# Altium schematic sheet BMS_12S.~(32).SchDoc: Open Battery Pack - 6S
size A3; Author: Morgane Vallée; Revision: 1.0; SheetNumber: 3; SheetTotal: 4
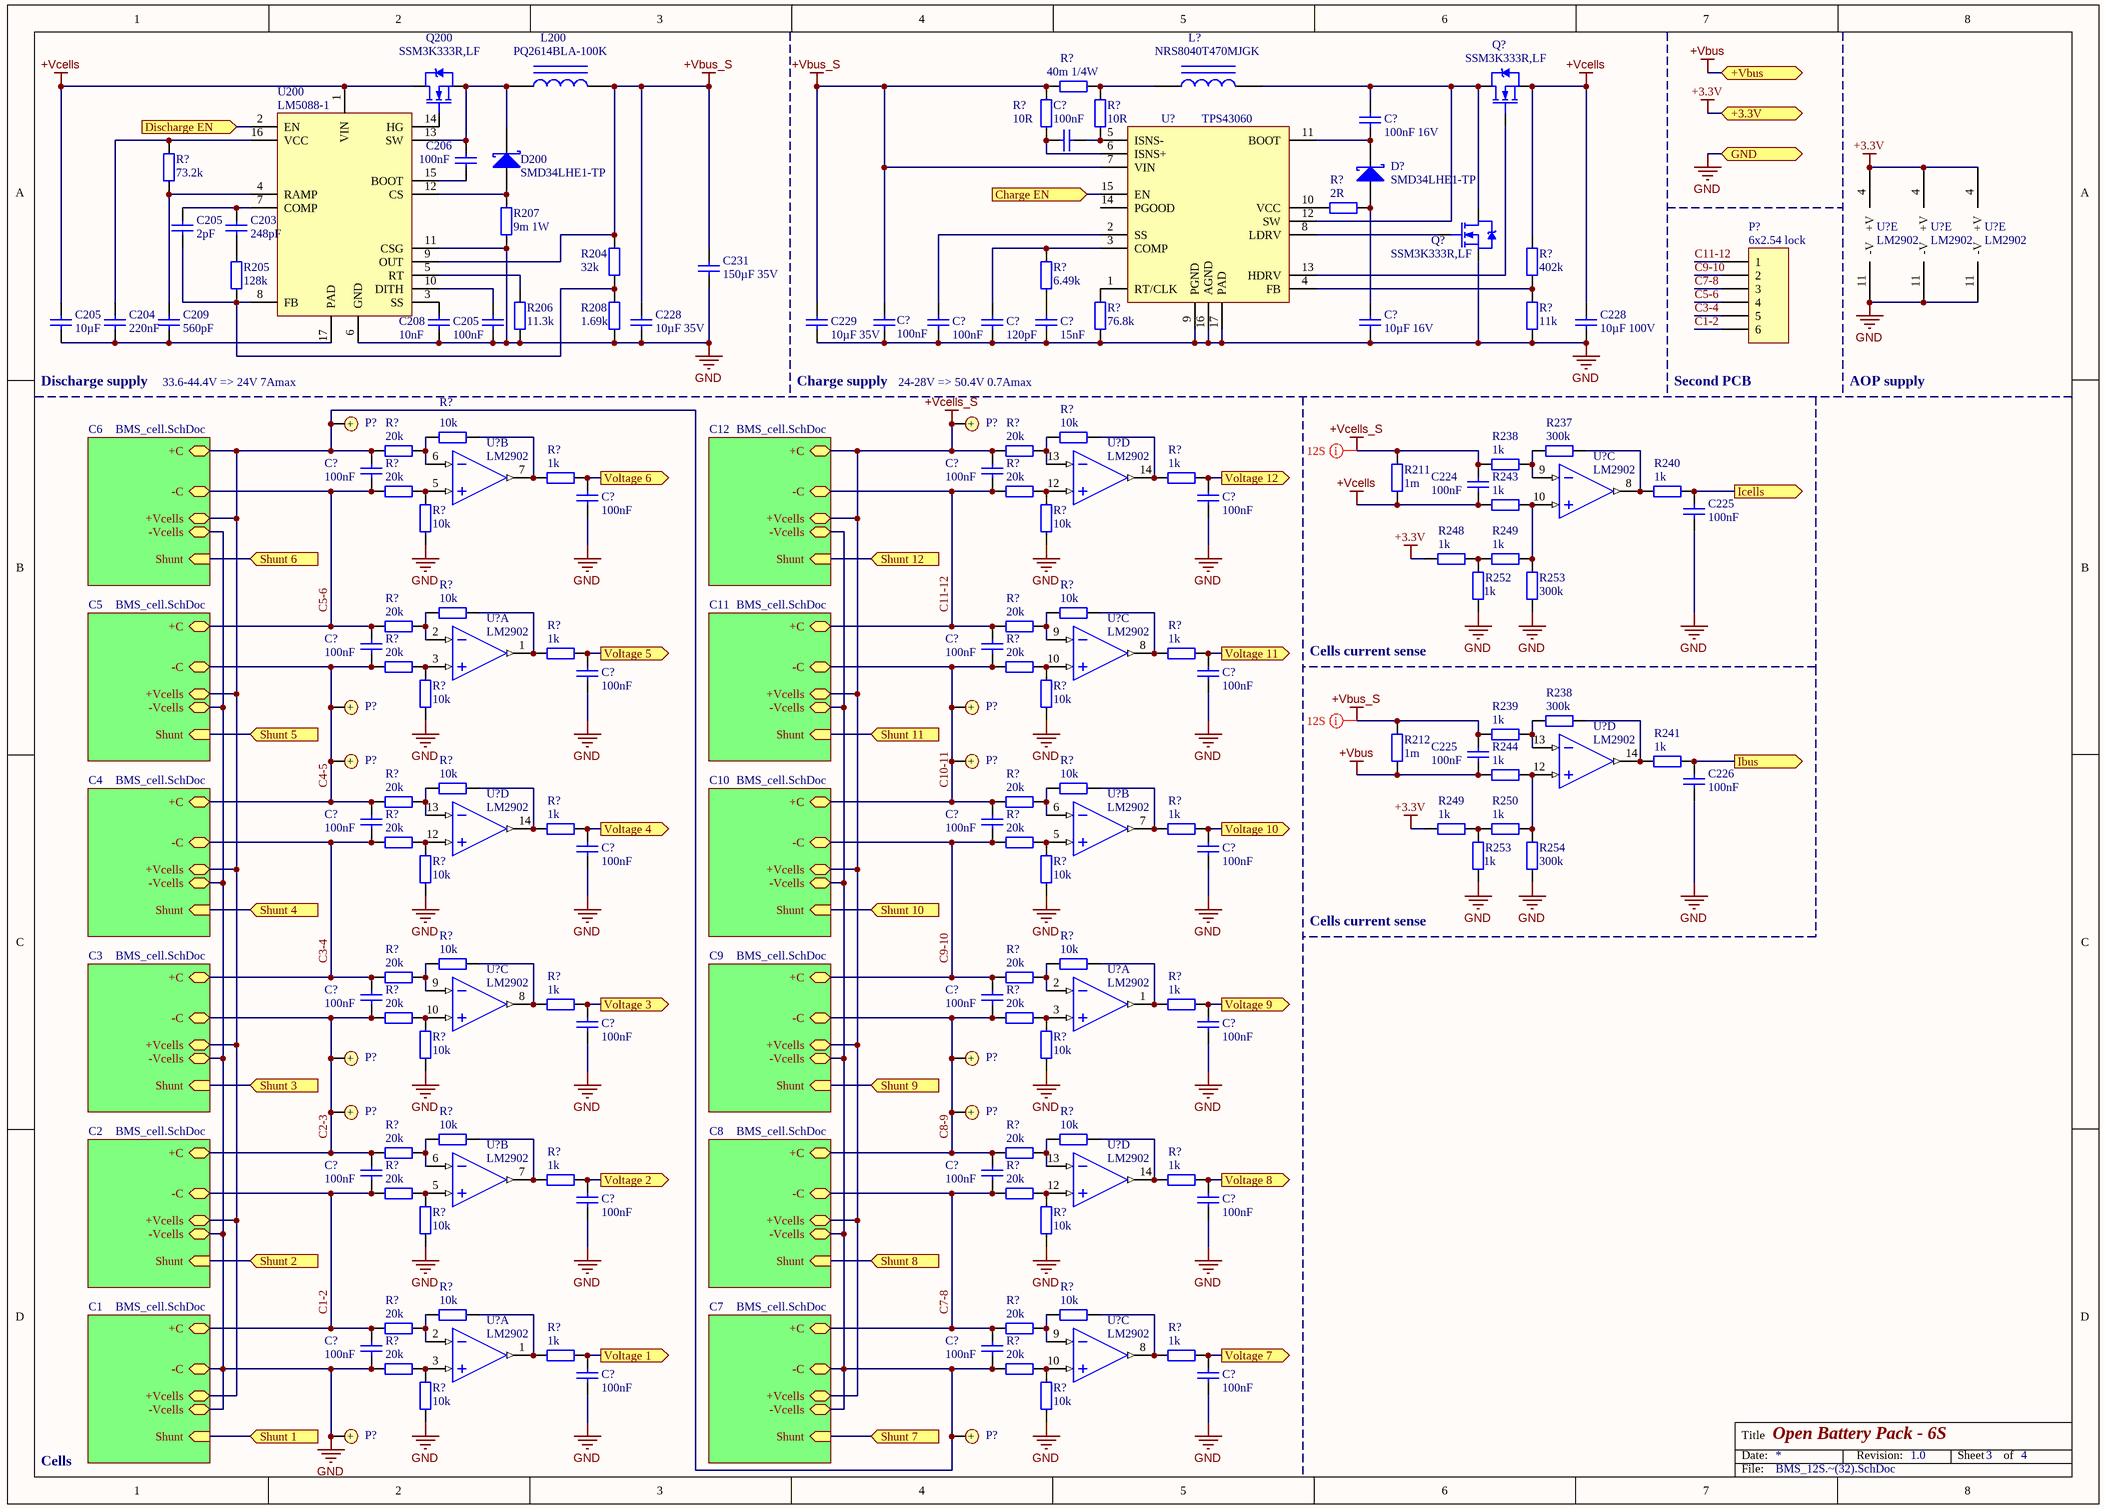
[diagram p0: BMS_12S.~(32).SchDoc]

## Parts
(Parts that share a designator on the sheet are numbered #1, #2 ... from top to bottom, then left to right.)
C203  248pF  [C0603]
C204  220nF  [C0603]
C205#1  2pF  [C0603]
C205#2  10µF  [C0603]
C205#3  100nF  [C0603]
C206  100nF  [C0603]
C208  10nF  [C0603]
C209  560pF  [C0603]
C224  100nF  [C0603]
C225#1  100nF  [C0603]
C225#2  100nF  [C0603]
C226  100nF  [C0603]
C228#1  10µF 35V  [C0603]
C228#2  10µF 100V  [C0603]
C229  10µF 35V  [C0603]
C231  150µF 35V  [C0603]
C?#1  100nF 16V  [C0603]
C?#2  100nF  [C0603]
C?#3  100nF  [C0603]
C?#4  120pF  [C0603]
C?#5  15nF  [C0603]
C?#6  10µF 16V  [C0805]
C?#7  100nF  [C0603]
C?#8  100nF  [C0603]
C?#9  100nF  [C0603]
C?#10  100nF  [C0603]
C?#11  100nF  [C0603]
C?#12  100nF  [C0603]
C?#13  100nF  [C0603]
C?#14  100nF  [C0603]
C?#15  100nF  [C0603]
C?#16  100nF  [C0603]
C?#17  100nF  [C0603]
C?#18  100nF  [C0603]
C?#19  100nF  [C0603]
C?#20  100nF  [C0603]
C?#21  100nF  [C0603]
C?#22  100nF  [C0603]
C?#23  100nF  [C0603]
C?#24  100nF  [C0603]
C?#25  100nF  [C0603]
C?#26  100nF  [C0603]
C?#27  100nF  [C0603]
C?#28  100nF  [C0603]
C?#29  100nF  [C0603]
C?#30  100nF  [C0603]
C?#31  100nF  [C0603]
D200  SMD34LHE1-TP  [SOD-123H]
D?  SMD34LHE1-TP  [SOD-123H]
L200  PQ2614BLA-100K  [SELF_SMD_8x8]
L?  NRS8040T470MJGK  [SELF_SMD_8x8]
P?#1  6x2.54 lock  [MOLEX KK 0022272061]
P?#2  Bat+  [Keystone 241]  (value not drawn)
P?#3  Bat+  [Keystone 241]  (value not drawn)
P?#4  Bat+  [Keystone 241]  (value not drawn)
P?#5  Bat+  [Keystone 241]  (value not drawn)
P?#6  Bat+  [Keystone 241]  (value not drawn)
P?#7  Bat+  [Keystone 241]  (value not drawn)
P?#8  Bat+  [Keystone 241]  (value not drawn)
P?#9  Bat+  [Keystone 241]  (value not drawn)
P?#10  Bat+  [Keystone 241]  (value not drawn)
P?#11  Bat+  [Keystone 241]  (value not drawn)
P?#12  Bat+  [Keystone 241]  (value not drawn)
P?#13  Bat+  [Keystone 241]  (value not drawn)
Q200  SSM3K333R,LF  [TI SOT-23-3 DBZ]
Q?#1  SSM3K333R,LF  [TI SOT-23-3 DBZ]
Q?#2  SSM3K333R,LF  [TI SOT-23-3 DBZ]
R204  32k  [R0603]
R205  128k  [R0603]
R206  11.3k  [R0603]
R207  9m 1W  [R1206]
R208  1.69k  [R0603]
R211  1m  [R1206]
R212  1m  [R1206]
R237  300k  [R0603]
R238#1  1k  [R0603]
R238#2  300k  [R0603]
R239  1k  [R0603]
R240  1k  [R0603]
R241  1k  [R0603]
R243  1k  [R0603]
R244  1k  [R0603]
R248  1k  [R0603]
R249#1  1k  [R0603]
R249#2  1k  [R0603]
R250  1k  [R0603]
R252  1k  [R0603]
R253#1  300k  [R0603]
R253#2  1k  [R0603]
R254  300k  [R0603]
R?#1  10R  [R0603]
R?#2  40m 1/4W  [R1206]
R?#3  10R  [R0603]
R?#4  73.2k  [R0603]
R?#5  2R  [R0603]
R?#6  402k  [R0603]
R?#7  6.49k  [R0603]
R?#8  76.8k  [R0603]
R?#9  11k  [R0603]
R?#10  10k  [R0603]
R?#11  10k  [R0603]
R?#12  20k  [R0603]
R?#13  20k  [R0603]
R?#14  1k  [R0603]
R?#15  1k  [R0603]
R?#16  20k  [R0603]
R?#17  10k  [R0603]
R?#18  20k  [R0603]
R?#19  10k  [R0603]
R?#20  10k  [R0603]
R?#21  10k  [R0603]
R?#22  20k  [R0603]
R?#23  20k  [R0603]
R?#24  1k  [R0603]
R?#25  1k  [R0603]
R?#26  20k  [R0603]
R?#27  10k  [R0603]
R?#28  20k  [R0603]
R?#29  10k  [R0603]
R?#30  10k  [R0603]
R?#31  10k  [R0603]
R?#32  20k  [R0603]
R?#33  20k  [R0603]
R?#34  1k  [R0603]
R?#35  1k  [R0603]
R?#36  20k  [R0603]
R?#37  10k  [R0603]
R?#38  20k  [R0603]
R?#39  10k  [R0603]
R?#40  10k  [R0603]
R?#41  10k  [R0603]
R?#42  20k  [R0603]
R?#43  20k  [R0603]
R?#44  1k  [R0603]
R?#45  1k  [R0603]
R?#46  20k  [R0603]
R?#47  10k  [R0603]
R?#48  20k  [R0603]
R?#49  10k  [R0603]
R?#50  10k  [R0603]
R?#51  10k  [R0603]
R?#52  20k  [R0603]
R?#53  20k  [R0603]
R?#54  1k  [R0603]
R?#55  1k  [R0603]
R?#56  20k  [R0603]
R?#57  10k  [R0603]
R?#58  20k  [R0603]
R?#59  10k  [R0603]
R?#60  10k  [R0603]
R?#61  10k  [R0603]
R?#62  20k  [R0603]
R?#63  20k  [R0603]
R?#64  1k  [R0603]
R?#65  1k  [R0603]
R?#66  20k  [R0603]
R?#67  10k  [R0603]
R?#68  20k  [R0603]
R?#69  10k  [R0603]
U200  LM5088-1  [TI MSOP-10 DGQ]
U?#1  TPS43060  [TI WQFN-16 RGH]
U?#2  LM2902  [Atmel SO-14 14S1]  (part E of 5)
U?#3  LM2902  [Atmel SO-14 14S1]  (part E of 5)
U?#4  LM2902  [Atmel SO-14 14S1]  (part E of 5)
U?#5  LM2902  [Atmel SO-14 14S1]  (part B of 5)
U?#6  LM2902  [Atmel SO-14 14S1]  (part D of 5)
U?#7  LM2902  [Atmel SO-14 14S1]  (part C of 5)
U?#8  LM2902  [Atmel SO-14 14S1]  (part A of 5)
U?#9  LM2902  [Atmel SO-14 14S1]  (part C of 5)
U?#10  LM2902  [Atmel SO-14 14S1]  (part D of 5)
U?#11  LM2902  [Atmel SO-14 14S1]  (part D of 5)
U?#12  LM2902  [Atmel SO-14 14S1]  (part B of 5)
U?#13  LM2902  [Atmel SO-14 14S1]  (part C of 5)
U?#14  LM2902  [Atmel SO-14 14S1]  (part A of 5)
U?#15  LM2902  [Atmel SO-14 14S1]  (part B of 5)
U?#16  LM2902  [Atmel SO-14 14S1]  (part D of 5)
U?#17  LM2902  [Atmel SO-14 14S1]  (part A of 5)
U?#18  LM2902  [Atmel SO-14 14S1]  (part C of 5)

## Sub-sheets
C1 = BMS_cell.SchDoc: -C, +C, +Vcells, -Vcells, Shunt (in)
C2 = BMS_cell.SchDoc: -C, +C, +Vcells, -Vcells, Shunt (in)
C3 = BMS_cell.SchDoc: -C, +C, +Vcells, -Vcells, Shunt (in)
C4 = BMS_cell.SchDoc: -C, +C, +Vcells, -Vcells, Shunt (in)
C5 = BMS_cell.SchDoc: -C, +C, +Vcells, -Vcells, Shunt (in)
C6 = BMS_cell.SchDoc: -C, +C, +Vcells, -Vcells, Shunt (in)
C7 = BMS_cell.SchDoc: -C, +C, +Vcells, -Vcells, Shunt (in)
C8 = BMS_cell.SchDoc: -C, +C, +Vcells, -Vcells, Shunt (in)
C9 = BMS_cell.SchDoc: -C, +C, +Vcells, -Vcells, Shunt (in)
C10 = BMS_cell.SchDoc: -C, +C, +Vcells, -Vcells, Shunt (in)
C11 = BMS_cell.SchDoc: -C, +C, +Vcells, -Vcells, Shunt (in)
C12 = BMS_cell.SchDoc: -C, +C, +Vcells, -Vcells, Shunt (in)

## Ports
+3.3V, +Vbus, Charge EN (in), Discharge EN (in), GND, Ibus (out), Icells (out), Shunt 1 (in), Shunt 2 (in), Shunt 3 (in), Shunt 4 (in), Shunt 5 (in), Shunt 6 (in), Shunt 7 (in), Shunt 8 (in), Shunt 9 (in), Shunt 10 (in), Shunt 11 (in), Shunt 12 (in), Voltage 1 (out), Voltage 2 (out), Voltage 3 (out), Voltage 4 (out), Voltage 5 (out), Voltage 6 (out), Voltage 7 (out), Voltage 8 (out), Voltage 9 (out), Voltage 10 (out), Voltage 11 (out), Voltage 12 (out)

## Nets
+3.3V: R248.2 R249#2.2 U?#2.4(+V) U?#3.4(+V) U?#4.4(+V) ; port +3.3V
+Vbus: C225#2.2 R212.1 R244.2 ; port +Vbus
+Vbus_S: C225#2.1 C228#1.1 C229.1 C231.1 C?#7.2 L200.2 R204.2 R212.2 R239.1 R?#1.1 R?#2.2 U200.9(OUT) U?#1.7(VIN)
+Vcells: C205#2.1 C224.2 C228#2.1 Q200.3(D) Q?#1.2(S) R211.1 R243.2 R?#6.2 U200.1(VIN)
+Vcells_S: C224.1 C?#9.1 P?#3.1 R211.2 R238#1.1 R?#13.1 ; sheet C7/+Vcells, sheet C8/+Vcells, sheet C9/+Vcells, sheet C10/+Vcells, sheet C11/+Vcells, sheet C12/+C, sheet C12/+Vcells
GND: C205#3.2 C208.2 C225#1.2 C226.2 C228#1.2 C228#2.2 C229.2 C231.2 C?#3.2 C?#4.2 C?#5.2 C?#6.2 C?#7.1 C?#10.2 C?#11.2 C?#14.2 C?#15.2 C?#18.2 C?#19.2 C?#22.2 C?#23.2 C?#26.2 C?#27.2 C?#28.2 C?#30.2 C?#31.2 P?#12.1 Q?#2.2(S) R206.1 R207.1 R208.1 R252.2 R253#1.1 R253#2.2 R254.1 R?#8.1 R?#9.1 R?#17.2 R?#19.2 R?#27.2 R?#29.2 R?#37.2 R?#39.2 R?#47.2 R?#49.2 R?#57.2 R?#59.2 R?#66.2 R?#67.2 R?#69.2 U200.6(GND) U200.11(CSG) U?#1.9(PGND) U?#1.16(AGND) U?#1.17(PAD) U?#2.11(-V) U?#3.11(-V) U?#4.11(-V) ; port GND, sheet C1/-C, sheet C1/-Vcells, sheet C2/-Vcells, sheet C3/-Vcells, sheet C4/-Vcells, sheet C5/-Vcells, sheet C6/-Vcells
C1-2: C?#24.2 C?#28.1 P?#1.6 R?#56.2 R?#62.1 ; sheet C1/+C, sheet C2/-C
C2-3: C?#20.2 C?#24.1 P?#8.1 P?#10.1 R?#46.2 R?#52.1 ; sheet C2/+C, sheet C3/-C
C3-4: C?#16.2 C?#20.1 P?#1.5 R?#36.2 R?#42.1 ; sheet C3/+C, sheet C4/-C
C4-5: C?#12.2 C?#16.1 P?#4.1 P?#6.1 R?#26.2 R?#32.1 ; sheet C4/+C, sheet C5/-C
C5-6: C?#8.2 C?#12.1 P?#1.4 R?#16.2 R?#22.1 ; sheet C5/+C, sheet C6/-C
C7-8: C?#25.2 C?#29.1 P?#1.3 R?#58.2 R?#63.1 ; sheet C7/+C, sheet C8/-C
C8-9: C?#21.2 C?#25.1 P?#9.1 P?#11.1 R?#48.2 R?#53.1 ; sheet C8/+C, sheet C9/-C
C9-10: C?#17.2 C?#21.1 P?#1.2 R?#38.2 R?#43.1 ; sheet C9/+C, sheet C10/-C
C10-11: C?#13.2 C?#17.1 P?#5.1 P?#7.1 R?#28.2 R?#33.1 ; sheet C10/+C, sheet C11/-C
C11-12: C?#9.2 C?#13.1 P?#1.1 R?#18.2 R?#23.1 ; sheet C11/+C, sheet C12/-C
Charge EN: U?#1.15(EN) ; port Charge EN
Discharge EN: U200.2(EN) ; port Discharge EN
Ibus: C226.1 R241.1 ; port Ibus
Icells: C225#1.1 R240.1 ; port Icells
Shunt 1: port Shunt 1, sheet C1/Shunt
Shunt 2: port Shunt 2, sheet C2/Shunt
Shunt 3: port Shunt 3, sheet C3/Shunt
Shunt 4: port Shunt 4, sheet C4/Shunt
Shunt 5: port Shunt 5, sheet C5/Shunt
Shunt 6: port Shunt 6, sheet C6/Shunt
Shunt 7: port Shunt 7, sheet C7/Shunt
Shunt 8: port Shunt 8, sheet C8/Shunt
Shunt 9: port Shunt 9, sheet C9/Shunt
Shunt 10: port Shunt 10, sheet C10/Shunt
Shunt 11: port Shunt 11, sheet C11/Shunt
Shunt 12: port Shunt 12, sheet C12/Shunt
Voltage 1: C?#30.1 R?#64.1 ; port Voltage 1
Voltage 2: C?#26.1 R?#54.1 ; port Voltage 2
Voltage 3: C?#22.1 R?#44.1 ; port Voltage 3
Voltage 4: C?#18.1 R?#34.1 ; port Voltage 4
Voltage 5: C?#14.1 R?#24.1 ; port Voltage 5
Voltage 6: C?#10.1 R?#14.1 ; port Voltage 6
Voltage 7: C?#31.1 R?#65.1 ; port Voltage 7
Voltage 8: C?#27.1 R?#55.1 ; port Voltage 8
Voltage 9: C?#23.1 R?#45.1 ; port Voltage 9
Voltage 10: C?#19.1 R?#35.1 ; port Voltage 10
Voltage 11: C?#15.1 R?#25.1 ; port Voltage 11
Voltage 12: C?#11.1 R?#15.1 ; port Voltage 12
NetC203_1: C203.1 C205#1.1 U200.7(COMP)
NetC203_2: C203.2 R205.2
NetC204_1: C204.1 R?#4.2 U200.16(VCC)
NetC204_2: C204.2 C205#2.2 C209.2 U200.17(PAD)
NetC205#1_2: C205#1.2 R204.1 R205.1 R208.2 U200.8(FB)
NetC205#3_1: C205#3.1 U200.10(DITH)
NetC206_1: C206.1 D200.3(K) L200.1 Q200.2(S) U200.13(SW)
NetC206_2: C206.2 U200.15(BOOT)
NetC208_1: C208.1 U200.3(SS)
NetC209_1: C209.1 R?#4.1 U200.4(RAMP)
NetC?#1_1: C?#1.1 L?.2 Q?#1.3(D) Q?#2.3(D) U?#1.12(SW)
NetC?#1_2: C?#1.2 D?.3(K) U?#1.11(BOOT)
NetC?#2_1: C?#2.1 R?#3.2 U?#1.5(ISNS-)
NetC?#2_2: C?#2.2 R?#1.2 U?#1.6(ISNS+)
NetC?#3_1: C?#3.1 U?#1.2(SS)
NetC?#4_1: C?#4.1 R?#7.2 U?#1.3(COMP)
NetC?#5_1: C?#5.1 R?#7.1
NetC?#6_1: C?#6.1 D?.1(A) R?#5.1
NetC?#8_1: C?#8.1 C?#29.2 P?#2.1 P?#13.1 R?#12.1 R?#68.2 ; sheet C1/+Vcells, sheet C2/+Vcells, sheet C3/+Vcells, sheet C4/+Vcells, sheet C5/+Vcells, sheet C6/+C, sheet C6/+Vcells, sheet C7/-C, sheet C7/-Vcells, sheet C8/-Vcells, sheet C9/-Vcells, sheet C10/-Vcells, sheet C11/-Vcells, sheet C12/-Vcells
NetD200_1: D200.1(A) R207.2 U200.12(CS)
NetL?_1: L?.1 R?#2.1 R?#3.1
NetQ200_1: Q200.1(G) U200.14(HG)
NetQ?#1_1: Q?#1.1(G) U?#1.13(HDRV)
NetQ?#2_1: Q?#2.1(G) U?#1.8(LDRV)
NetR206_2: R206.2 U200.5(RT)
NetR237_1: R237.1 R240.2 U?#7.8(OUT)
NetR237_2: R237.2 R238#1.2 U?#7.9(IN-)
NetR238#2_1: R238#2.1 R241.2 U?#10.14(OUT)
NetR238#2_2: R238#2.2 R239.2 U?#10.13(IN-)
NetR243_1: R243.1 R249#1.1 R253#1.2 U?#7.10(IN+)
NetR244_1: R244.1 R250.1 R254.2 U?#10.12(IN+)
NetR248_1: R248.1 R249#1.2 R252.1
NetR249#2_1: R249#2.1 R250.2 R253#2.1
NetR?#5_2: R?#5.2 U?#1.10(VCC)
NetR?#6_1: R?#6.1 R?#9.2 U?#1.4(FB)
NetR?#8_2: R?#8.2 U?#1.1(RT/CLK)
NetR?#10_1: R?#10.1 R?#12.2 U?#5.6(IN-)
NetR?#10_2: R?#10.2 R?#14.2 U?#5.7(OUT)
NetR?#11_1: R?#11.1 R?#13.2 U?#6.13(IN-)
NetR?#11_2: R?#11.2 R?#15.2 U?#6.14(OUT)
NetR?#16_1: R?#16.1 R?#17.1 U?#5.5(IN+)
NetR?#18_1: R?#18.1 R?#19.1 U?#6.12(IN+)
NetR?#20_1: R?#20.1 R?#22.2 U?#8.2(IN-)
NetR?#20_2: R?#20.2 R?#24.2 U?#8.1(OUT)
NetR?#21_1: R?#21.1 R?#23.2 U?#9.9(IN-)
NetR?#21_2: R?#21.2 R?#25.2 U?#9.8(OUT)
NetR?#26_1: R?#26.1 R?#27.1 U?#8.3(IN+)
NetR?#28_1: R?#28.1 R?#29.1 U?#9.10(IN+)
NetR?#30_1: R?#30.1 R?#32.2 U?#11.13(IN-)
NetR?#30_2: R?#30.2 R?#34.2 U?#11.14(OUT)
NetR?#31_1: R?#31.1 R?#33.2 U?#12.6(IN-)
NetR?#31_2: R?#31.2 R?#35.2 U?#12.7(OUT)
NetR?#36_1: R?#36.1 R?#37.1 U?#11.12(IN+)
NetR?#38_1: R?#38.1 R?#39.1 U?#12.5(IN+)
NetR?#40_1: R?#40.1 R?#42.2 U?#13.9(IN-)
NetR?#40_2: R?#40.2 R?#44.2 U?#13.8(OUT)
NetR?#41_1: R?#41.1 R?#43.2 U?#14.2(IN-)
NetR?#41_2: R?#41.2 R?#45.2 U?#14.1(OUT)
NetR?#46_1: R?#46.1 R?#47.1 U?#13.10(IN+)
NetR?#48_1: R?#48.1 R?#49.1 U?#14.3(IN+)
NetR?#50_1: R?#50.1 R?#52.2 U?#15.6(IN-)
NetR?#50_2: R?#50.2 R?#54.2 U?#15.7(OUT)
NetR?#51_1: R?#51.1 R?#53.2 U?#16.13(IN-)
NetR?#51_2: R?#51.2 R?#55.2 U?#16.14(OUT)
NetR?#56_1: R?#56.1 R?#57.1 U?#15.5(IN+)
NetR?#58_1: R?#58.1 R?#59.1 U?#16.12(IN+)
NetR?#60_1: R?#60.1 R?#62.2 U?#17.2(IN-)
NetR?#60_2: R?#60.2 R?#64.2 U?#17.1(OUT)
NetR?#61_1: R?#61.1 R?#63.2 U?#18.9(IN-)
NetR?#61_2: R?#61.2 R?#65.2 U?#18.8(OUT)
NetR?#66_1: R?#66.1 R?#67.1 U?#17.3(IN+)
NetR?#68_1: R?#68.1 R?#69.1 U?#18.10(IN+)

Not connected (* = marked no-connect by the designer): U?#1 14(PGOOD)

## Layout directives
net class 12S: +Vbus_S, +Vcells_S

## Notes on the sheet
- Discharge supply
- 33.6-44.4V => 24V 7Amax
- Charge supply
- 24-28V => 50.4V 0.7Amax
- (near P?#1) Second PCB
- AOP supply
- Cells current sense
- (near R253#2) Cells current sense
- Cells

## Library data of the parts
C203 C204 C205#1-C205#3 C206 C208 C209 C224 C225#1 C225#2 C226 C228#1 C228#2 C229 C231 C?#1-C?#31 = Cap: Capacitor
D200 D? = Diode BAT17
L200 L? = Inductor Iron: Magnetic-Core Inductor
P?#1 = Header 6: Header, 6-Pin
P?#2-P?#13 = Bat+: Battery contact +
Q200 Q?#1 Q?#2 = MOSFET_N
R204-R208 R211 R212 R237 R238#1 R238#2 R239-R241 R243 R244 R248 R249#1 R249#2 R250 R252 R253#1 R253#2 R254 R?#1-R?#69 = Res2: Resistor
U200 = LM5088-1: Wide Input Range Non-Synchronous Buck Controller
U?#1 = TPS43060: Low Quiescent Current Synchronous Boost  DC-DC Controller With Wide VIN Range
U?#2-U?#18 = LM2902: Low-power quad operational amplifiers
